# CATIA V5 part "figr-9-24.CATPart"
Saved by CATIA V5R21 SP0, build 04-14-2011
Part number: Part2
Bounding box of the stored display mesh (mm): x -72 to 72, y -80 to 90, z -20 to 41.296
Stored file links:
  D:\CATIA V5R21 E-RESOURCES\CATIA-V5R21\catia-v5r21-prt\c09-catia-v5r20-prt\c09-catia-v5r21-figr-9-24.CATPart
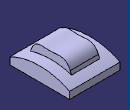
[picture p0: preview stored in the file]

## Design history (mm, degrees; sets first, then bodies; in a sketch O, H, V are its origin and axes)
Body1 (main body)
  Sketch1 on yz-plane, origin (0, 0, 0), H (0, 1, 0), V (0, 0, 1)
    arc A1 centre (5, -170) radius 190.0658 from (-80, 0) to (90, 0) cw
    point P2 (-80, 0)
    point P3 (0, 20)
    line L1 (-80, 0) -> (-80, -20)
    line L2 (-80, -20) -> (90, -20)
    line L3 (90, -20) -> (90, 0)
    coincidence: P2 H, A1 P3, P3 V
    vertical: L1 V, L3 V
    horizontal: L2 H
  Pad1: profile Sketch1, direction (1, 0, 0), length 72, mirrored extent
  Sketch2 on yz-plane, origin (0, 0, 0), H (0, 1, 0), V (0, 0, 1)
    spline S1 through (60, 20) (40, 40) (10, 40) (-10, 40) (-30, 40) (-50, 20)
  Sketch3 on zx-plane, origin (0, 0, 0), H (-1, 0, 0), V (0, 0, 1)
    line L1 (-40, 30) -> (40, 30)
    horizontal: L1 H
  Rib1: profile Sketch2, centre curve Sketch3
